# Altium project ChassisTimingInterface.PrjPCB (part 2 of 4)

## Sheet ChassisTimingInterface5.SchDoc: FPGA Interface
size C; DocumentNumber: 6; Revision: C; SheetNumber: 6; SheetTotal: 12
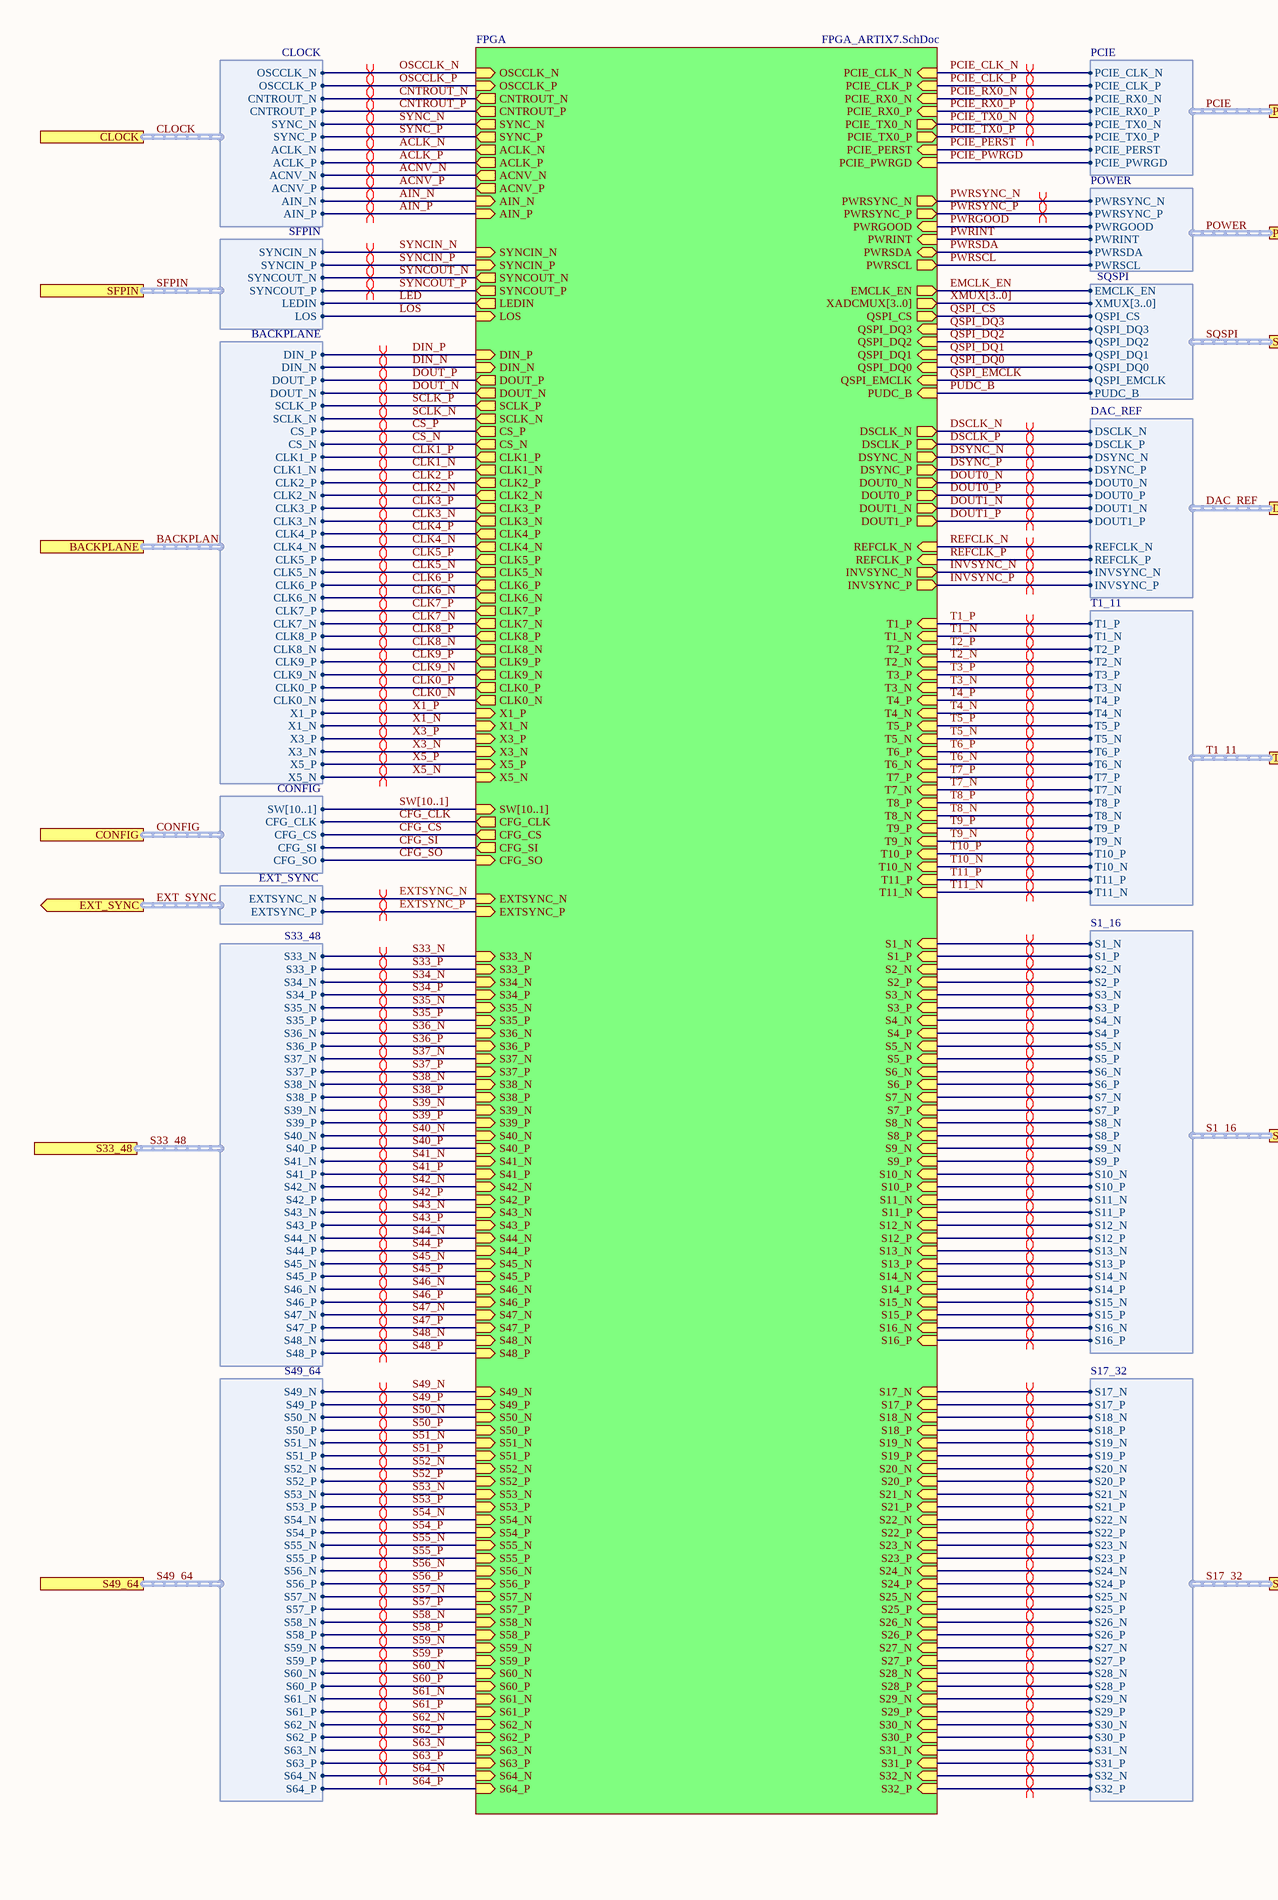
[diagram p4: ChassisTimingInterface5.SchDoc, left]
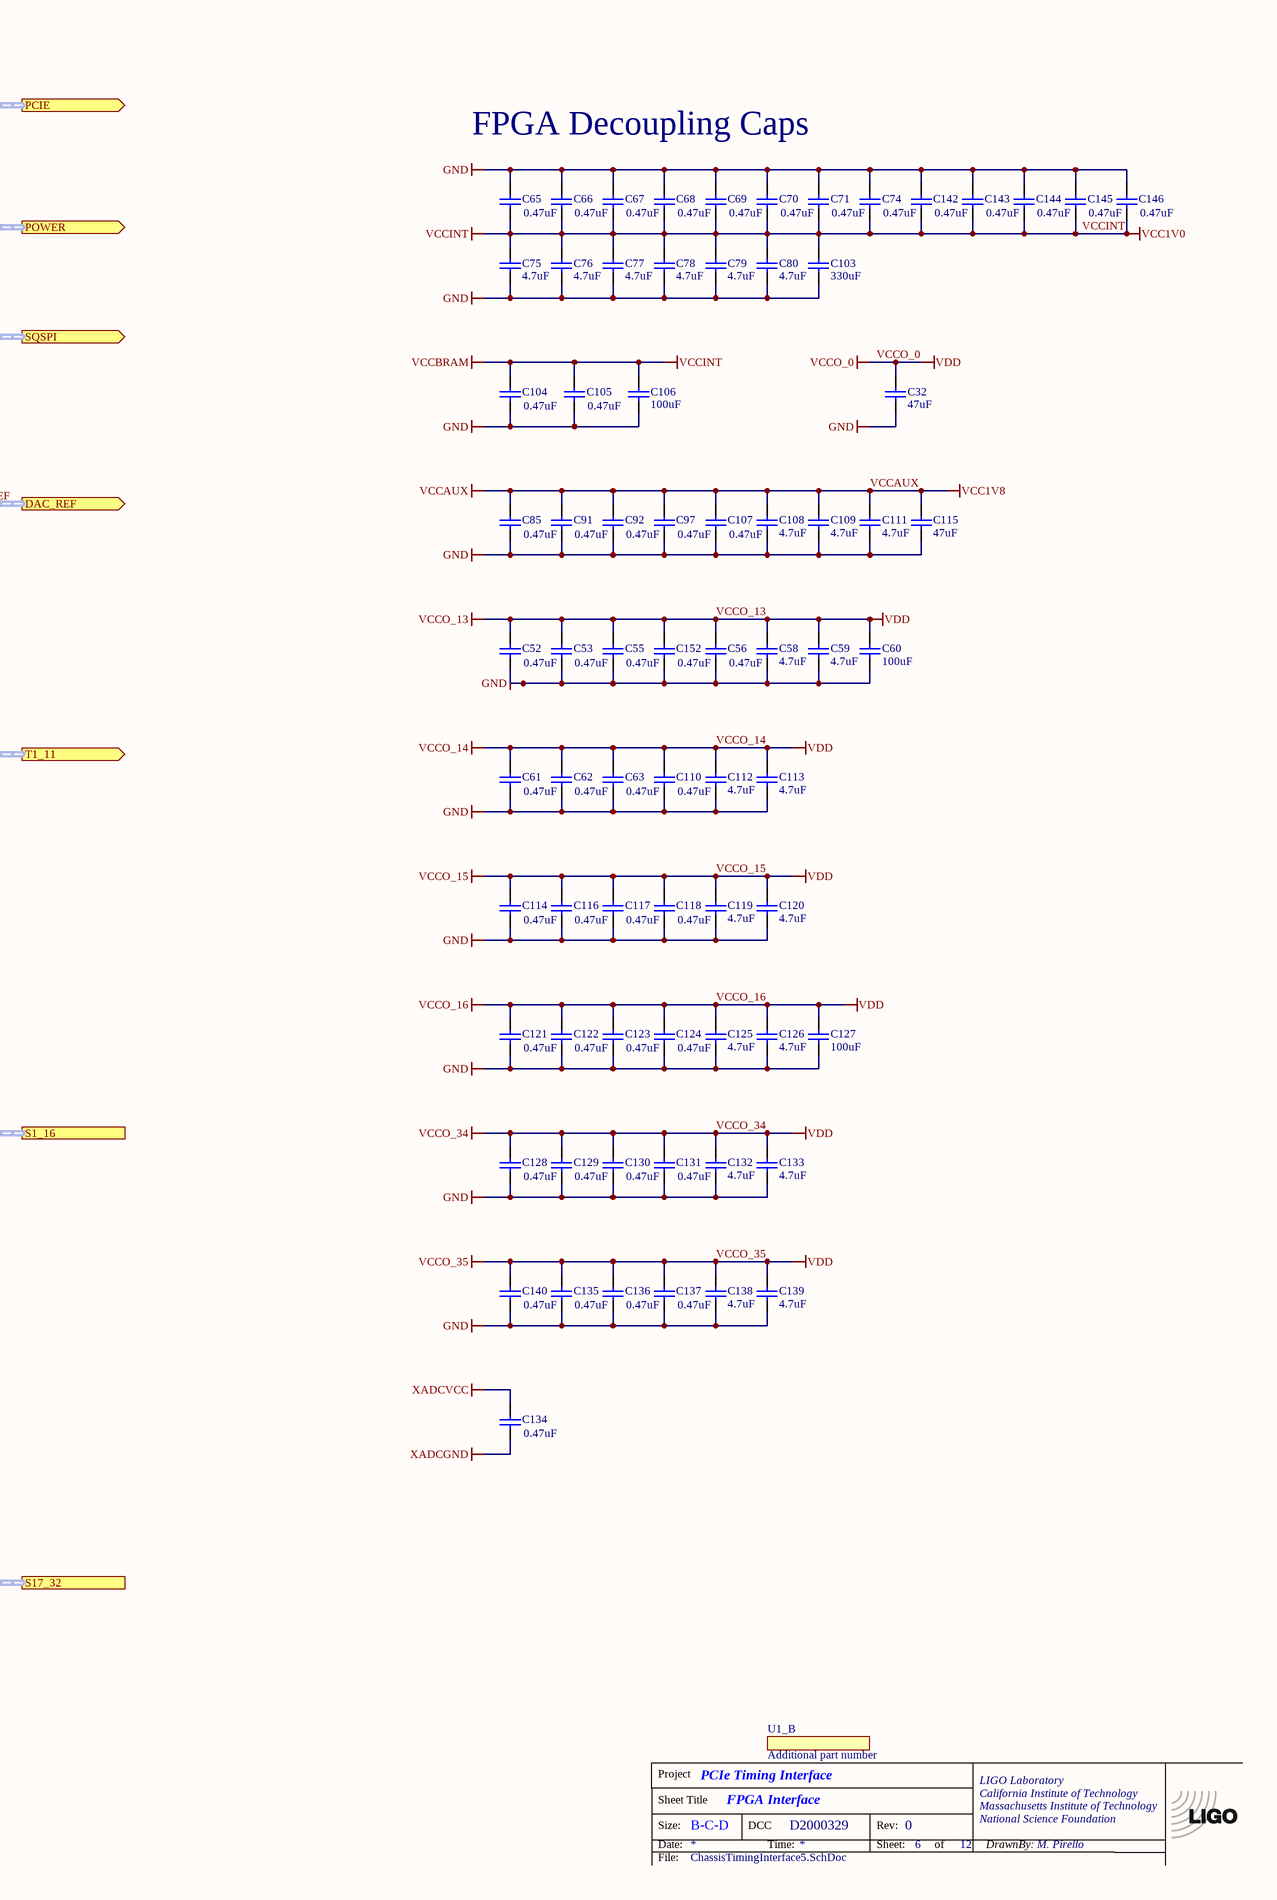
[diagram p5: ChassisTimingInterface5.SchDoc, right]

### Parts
(Parts that share a designator on the sheet are numbered #1, #2 ... from top to bottom, then left to right.)
*?#3  TitleBlock  (value not drawn)  (graphical)
C32  47uF  [CC3225-1210]
C52  0.47uF  [CAPC0603X33X15NL03T05]
C53  0.47uF  [CAPC0603X33X15NL03T05]
C55  0.47uF  [CAPC0603X33X15NL03T05]
C56  0.47uF  [CAPC0603X33X15NL03T05]
C58  4.7uF  [CC1608-0603]
C59  4.7uF  [CC1608-0603]
C60  100uF  [CC3225-1210]
C61  0.47uF  [CAPC0603X33X15NL03T05]
C62  0.47uF  [CAPC0603X33X15NL03T05]
C63  0.47uF  [CAPC0603X33X15NL03T05]
C65  0.47uF  [CAPC0603X33X15NL03T05]
C66  0.47uF  [CAPC0603X33X15NL03T05]
C67  0.47uF  [CAPC0603X33X15NL03T05]
C68  0.47uF  [CAPC0603X33X15NL03T05]
C69  0.47uF  [CAPC0603X33X15NL03T05]
C70  0.47uF  [CAPC0603X33X15NL03T05]
C71  0.47uF  [CAPC0603X33X15NL03T05]
C74  0.47uF  [CAPC0603X33X15NL03T05]
C75  4.7uF  [CC1608-0603]
C76  4.7uF  [CC1608-0603]
C77  4.7uF  [CC1608-0603]
C78  4.7uF  [CC1608-0603]
C79  4.7uF  [CC1608-0603]
C80  4.7uF  [CC1608-0603]
C85  0.47uF  [CAPC0603X33X15NL03T05]
C91  0.47uF  [CAPC0603X33X15NL03T05]
C92  0.47uF  [CAPC0603X33X15NL03T05]
C97  0.47uF  [CAPC0603X33X15NL03T05]
C103  330uF  [CC3225-1210]
C104  0.47uF  [CAPC0603X33X15NL03T05]
C105  0.47uF  [CAPC0603X33X15NL03T05]
C106  100uF  [CC3225-1210]
C107  0.47uF  [CAPC0603X33X15NL03T05]
C108  4.7uF  [CC1608-0603]
C109  4.7uF  [CC1608-0603]
C110  0.47uF  [CAPC0603X33X15NL03T05]
C111  4.7uF  [CC1608-0603]
C112  4.7uF  [CC1608-0603]
C113  4.7uF  [CC1608-0603]
C114  0.47uF  [CAPC0603X33X15NL03T05]
C115  47uF  [CC3225-1210]
C116  0.47uF  [CAPC0603X33X15NL03T05]
C117  0.47uF  [CAPC0603X33X15NL03T05]
C118  0.47uF  [CAPC0603X33X15NL03T05]
C119  4.7uF  [CC1608-0603]
C120  4.7uF  [CC1608-0603]
C121  0.47uF  [CAPC0603X33X15NL03T05]
C122  0.47uF  [CAPC0603X33X15NL03T05]
C123  0.47uF  [CAPC0603X33X15NL03T05]
C124  0.47uF  [CAPC0603X33X15NL03T05]
C125  4.7uF  [CC1608-0603]
C126  4.7uF  [CC1608-0603]
C127  100uF  [CC3225-1210]
C128  0.47uF  [CAPC0603X33X15NL03T05]
C129  0.47uF  [CAPC0603X33X15NL03T05]
C130  0.47uF  [CAPC0603X33X15NL03T05]
C131  0.47uF  [CAPC0603X33X15NL03T05]
C132  4.7uF  [CC1608-0603]
C133  4.7uF  [CC1608-0603]
C134  0.47uF  [CAPC0603X33X15NL03T05]
C135  0.47uF  [CAPC0603X33X15NL03T05]
C136  0.47uF  [CAPC0603X33X15NL03T05]
C137  0.47uF  [CAPC0603X33X15NL03T05]
C138  4.7uF  [CC1608-0603]
C139  4.7uF  [CC1608-0603]
C140  0.47uF  [CAPC0603X33X15NL03T05]
C142  0.47uF  [CAPC0603X33X15NL03T05]
C143  0.47uF  [CAPC0603X33X15NL03T05]
C144  0.47uF  [CAPC0603X33X15NL03T05]
C145  0.47uF  [CAPC0603X33X15NL03T05]
C146  0.47uF  [CAPC0603X33X15NL03T05]
C152  0.47uF  [CAPC0603X33X15NL03T05]
U1_B  Additional part number  (mechanical)

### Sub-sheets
FPGA = FPGA_ARTIX7.SchDoc: SW[10..1] (in), XADCMUX[3..0] (out), S1_N (in), S1_P (in), S2_N (in), S2_P (in), S3_N (in), S3_P (in), S4_N (in), S4_P (in), S5_N (in), S5_P (in), S6_N (in), S6_P (in), S7_N (in), S7_P (in), S8_N (in), S8_P (in), S9_P (in), S9_N (in), S10_P (in), S10_N (in), S11_P (in), S11_N (in), S12_P (in), S12_N (in), S13_P (in), S13_N (in), S14_P (in), S14_N (in), S15_P (in), S15_N (in), S16_P (in), S16_N (in), S33_N (in), S33_P (in), S34_N (in), S34_P (in), S35_N (in), S35_P (in), S36_N (in), S36_P (in), S37_N (in), S37_P (in), S38_N (in), S38_P (in), S39_N (in), S39_P (in), S40_N (in), S40_P (in), S42_N (in), S41_P (in), S42_P (in), S43_N (in), S43_P (in), S44_N (in), S44_P (in), S45_N (in), S45_P (in), S46_N (in), S46_P (in), S47_N (in), S47_P (in), S48_N (in), S48_P (in), S41_N (in), T9_P (in), T9_N (in), T8_P (in), T8_N (in), T7_P (in), T7_N (in), T6_P (in), T6_N (in), T5_P (in), T5_N (in), T4_P (in), T4_N (in), T3_P (in), T3_N (in), T2_P (in), T2_N (in), T11_P (in), T11_N (in), T10_P (in), T10_N (in), T1_P (in), T1_N (in), REFCLK_N (in), REFCLK_P (in), PCIE_PERST (in), PCIE_RX0_N (in), PCIE_TX0_N (out), PCIE_RX0_P (in), PCIE_TX0_P (out), PCIE_CLK_N (in), PCIE_CLK_P (in), PWRSYNC_N (out), PWRSYNC_P (out), PWRINT (in), PWRGOOD (in), PWRSDA (bidir), PWRSCL (out), QSPI_DQ0 (in), QSPI_CS (out), QSPI_DQ2 (in), QSPI_DQ3 (in), QSPI_DQ1 (in), CNTROUT_N (out), CNTROUT_P (out), OSCCLK_N (in), OSCCLK_P (in), SYNC_N (out), SYNC_P (out), ACLK_N (out), ACLK_P (out), ACNV_N (out), ACNV_P (out), AIN_N (in), AIN_P (in), LEDIN (out), LOS (in), SYNCIN_N (in), SYNCIN_P (in), SYNCOUT_N (out), SYNCOUT_P (out), CS_P (out), CS_N (out), SCLK_P (out), SCLK_N (out), DOUT_P (out), DOUT_N (out), DIN_P (in), DIN_N (in), CFG_CLK (out), CFG_CS (out), CFG_SI (out), CFG_SO (in), INVSYNC_N (out), INVSYNC_P (out), CLK9_P (out), CLK9_N (out), CLK8_P (out), CLK8_N (out), CLK7_P (out), CLK7_N (out), CLK6_P (out), CLK6_N (out), CLK5_P (out), CLK5_N (out), CLK4_P (out), CLK4_N (out), CLK3_P (out), CLK3_N (out), CLK2_P (out), CLK2_N (out), CLK0_P (out), CLK0_N (out), CLK1_P (out), CLK1_N (out), X1_P (in), X1_N (in), X3_P (in), X3_N (in), X5_P (in), X5_N (in), S49_N (in), S49_P (in), S50_N (in), S50_P (in), S51_N (in), S51_P (in), S52_N (in), S52_P (in), S53_N (in), S53_P (in), S54_N (in), S54_P (in), S55_N (in), S55_P (in), S56_N (in), S56_P (in), S57_N (in), S57_P (in), S58_N (in), S58_P (in), S59_N (in), S59_P (in), S60_N (in), S60_P (in), S61_N (in), S61_P (in), S62_N (in), S62_P (in), S63_N (in), S63_P (in), S64_N (in), S64_P (in), S29_P (in), S17_N (in), S17_P (in), S18_N (in), S18_P (in), S19_N (in), S19_P (in), S20_N (in), S20_P (in), S21_N (in), S21_P (in), S22_N (in), S22_P (in), S23_N (in), S23_P (in), S24_N (in), S24_P (in), S25_N (in), S25_P (in), S26_N (in), S26_P (in), S27_N (in), S27_P (in), S28_N (in), S28_P (in), S29_N (in), S30_N (in), S30_P (in), S31_N (in), S31_P (in), S32_N (in), S32_P (in), QSPI_EMCLK (in), EXTSYNC_N (in), EXTSYNC_P (in), DOUT0_N (out), DSCLK_P (out), DSCLK_N (out), DOUT0_P (out), DSYNC_N (out), DOUT1_P (out), DSYNC_P (out), DOUT1_N (out), PUDC_B (in), PCIE_PWRGD (in), EMCLK_EN (out)

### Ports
BACKPLANE (harness BACKPLANE), CLOCK (harness CLOCK), CONFIG (harness CONFIG), DAC_REF (out, harness DAC_REF), EXT_SYNC (out, harness EXT_SYNC), PCIE (out, harness PCIE), POWER (out, harness POWER), S1_16 (harness S1_16), S17_32 (harness S17_32), S33_48 (harness S33_48), S49_64 (harness S49_64), SFPIN (harness SFPIN), SQSPI (out, harness SQSPI), T1_11 (out, harness T1_11)

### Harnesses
S1_16: S1_N, S1_P, S2_N, S2_P, S3_N, S3_P, S4_N, S4_P, S5_N, S5_P, S6_N, S6_P, S7_N, S7_P, S8_N, S8_P, S9_N, S9_P, S10_N, S10_P, S11_N, S11_P, S12_N, S12_P, S13_N, S13_P, S14_N, S14_P, S15_N, S15_P, S16_N, S16_P
S17_32: S17_N, S17_P, S18_N, S18_P, S19_N, S19_P, S20_N, S20_P, S21_N, S21_P, S22_N, S22_P, S23_N, S23_P, S24_N, S24_P, S25_N, S25_P, S26_N, S26_P, S27_N, S27_P, S28_N, S28_P, S29_N, S29_P, S30_N, S30_P, S31_N, S31_P, S32_N, S32_P
S33_48: S33_N, S33_P, S34_N, S34_P, S35_N, S35_P, S36_N, S36_P, S37_N, S37_P, S38_N, S38_P, S39_N, S39_P, S40_N, S40_P, S41_N, S41_P, S42_N, S42_P, S43_N, S43_P, S44_N, S44_P, S45_N, S45_P, S46_N, S46_P, S47_N, S47_P, S48_N, S48_P
S49_64: S49_N, S49_P, S50_N, S50_P, S51_N, S51_P, S52_N, S52_P, S53_N, S53_P, S54_N, S54_P, S55_N, S55_P, S56_N, S56_P, S57_N, S57_P, S58_N, S58_P, S59_N, S59_P, S60_N, S60_P, S61_N, S61_P, S62_N, S62_P, S63_N, S63_P, S64_N, S64_P
T1_11: T1_P, T1_N, T2_P, T2_N, T3_P, T3_N, T4_P, T4_N, T5_P, T5_N, T6_P, T6_N, T7_P, T7_N, T8_P, T8_N, T9_P, T9_N, T10_P, T10_N, T11_P, T11_N
BACKPLANE: DIN_P, DIN_N, DOUT_P, DOUT_N, SCLK_P, SCLK_N, CS_P, CS_N, CLK1_P, CLK1_N, CLK2_P, CLK2_N, CLK3_P, CLK3_N, CLK4_P, CLK4_N, CLK5_P, CLK5_N, CLK6_P, CLK6_N, CLK7_P, CLK7_N, CLK8_P, CLK8_N, CLK9_P, CLK9_N, CLK0_P, CLK0_N, X1_P, X1_N, X3_P, X3_N, X5_P, X5_N
SFPIN: SYNCIN_N, SYNCIN_P, SYNCOUT_N, SYNCOUT_P, LEDIN, LOS
CLOCK: OSCCLK_N, OSCCLK_P, CNTROUT_N, CNTROUT_P, SYNC_N, SYNC_P, ACLK_P, ACLK_N, ACNV_P, ACNV_N, AIN_P, AIN_N
CONFIG: CFG_CLK, CFG_CS, CFG_SI, CFG_SO, SW[10..1]
SQSPI: QSPI_CS, QSPI_DQ3, QSPI_DQ2, QSPI_DQ1, QSPI_DQ0, QSPI_EMCLK, PUDC_B, XMUX[3..0], EMCLK_EN
PCIE: PCIE_CLK_N, PCIE_CLK_P, PCIE_RX0_N, PCIE_RX0_P, PCIE_TX0_N, PCIE_TX0_P, PCIE_PERST, PCIE_PWRGD
POWER: PWRSYNC_N, PWRSYNC_P, PWRGOOD, PWRINT, PWRSDA, PWRSCL
DAC_REF: DSCLK_N, DSCLK_P, DSYNC_N, DSYNC_P, DOUT0_N, DOUT0_P, DOUT1_N, DOUT1_P, REFCLK_N, REFCLK_P, INVSYNC_N, INVSYNC_P
EXT_SYNC: EXTSYNC_P, EXTSYNC_N

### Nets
GND: C32.1 C52.1 C53.1 C55.1 C56.1 C58.1 C59.1 C60.1 C61.1 C62.1 C63.1 C65.2 C66.2 C67.2 C68.2 C69.2 C70.2 C71.2 C74.2 C75.1 C76.1 C77.1 C78.1 C79.1 C80.1 C85.1 C91.1 C92.1 C97.1 C103.1 C104.1 C105.1 C106.1 C107.1 C108.1 C109.1 C110.1 C111.1 C112.1 C113.1 C114.1 C115.1 C116.1 C117.1 C118.1 C119.1 C120.1 C121.1 C122.1 C123.1 C124.1 C125.1 C126.1 C127.1 C128.1 C129.1 C130.1 C131.1 C132.1 C133.1 C135.1 C136.1 C137.1 C138.1 C139.1 C140.1 C142.2 C143.2 C144.2 C145.2 C146.2 C152.1
VCC1V8: C85.2 C91.2 C92.2 C97.2 C107.2 C108.2 C109.2 C111.2 C115.2  [also labelled VCCAUX]
VCCINT: C65.1 C66.1 C67.1 C68.1 C69.1 C70.1 C71.1 C74.1 C75.2 C76.2 C77.2 C78.2 C79.2 C80.2 C103.2 C104.2 C105.2 C106.2 C142.1 C143.1 C144.1 C145.1 C146.1  [also labelled VCC1V0, VCCBRAM]
VDD: C32.2 C52.2 C53.2 C55.2 C56.2 C58.2 C59.2 C60.2 C61.2 C62.2 C63.2 C110.2 C112.2 C113.2 C114.2 C116.2 C117.2 C118.2 C119.2 C120.2 C121.2 C122.2 C123.2 C124.2 C125.2 C126.2 C127.2 C128.2 C129.2 C130.2 C131.2 C132.2 C133.2 C135.2 C136.2 C137.2 C138.2 C139.2 C140.2 C152.2  [also labelled VCCO_0, VCCO_13, VCCO_14, VCCO_15, VCCO_16, VCCO_34, VCCO_35]
XADCGND: C134.1
XADCVCC: C134.2
ACLK_N: sheet FPGA/ACLK_N, port CLOCK.ACLK_N  [project net CLOCK.ACLK_N]
ACLK_P: sheet FPGA/ACLK_P, port CLOCK.ACLK_P  [project net CLOCK.ACLK_P]
ACNV_N: sheet FPGA/ACNV_N, port CLOCK.ACNV_N  [project net CLOCK.ACNV_N]
ACNV_P: sheet FPGA/ACNV_P, port CLOCK.ACNV_P  [project net CLOCK.ACNV_P]
AIN_N: sheet FPGA/AIN_N, port CLOCK.AIN_N  [project net CLOCK.AIN_N]
AIN_P: sheet FPGA/AIN_P, port CLOCK.AIN_P  [project net CLOCK.AIN_P]
CFG_CLK: sheet FPGA/CFG_CLK, port CONFIG.CFG_CLK
CFG_CS: sheet FPGA/CFG_CS, port CONFIG.CFG_CS
CFG_SI: sheet FPGA/CFG_SI, port CONFIG.CFG_SI
CFG_SO: sheet FPGA/CFG_SO, port CONFIG.CFG_SO
CLK0_N: sheet FPGA/CLK0_N, port BACKPLANE.CLK0_N  [project net BACKPLANE.CLK0_N]
CLK0_P: sheet FPGA/CLK0_P, port BACKPLANE.CLK0_P  [project net BACKPLANE.CLK0_P]
CLK1_N: sheet FPGA/CLK1_N, port BACKPLANE.CLK1_N  [project net BACKPLANE.CLK1_N]
CLK1_P: sheet FPGA/CLK1_P, port BACKPLANE.CLK1_P  [project net BACKPLANE.CLK1_P]
CLK2_N: sheet FPGA/CLK2_N, port BACKPLANE.CLK2_N  [project net BACKPLANE.CLK2_N]
CLK2_P: sheet FPGA/CLK2_P, port BACKPLANE.CLK2_P  [project net BACKPLANE.CLK2_P]
CLK3_N: sheet FPGA/CLK3_N, port BACKPLANE.CLK3_N  [project net BACKPLANE.CLK3_N]
CLK3_P: sheet FPGA/CLK3_P, port BACKPLANE.CLK3_P  [project net BACKPLANE.CLK3_P]
CLK4_N: sheet FPGA/CLK4_N, port BACKPLANE.CLK4_N  [project net BACKPLANE.CLK4_N]
CLK4_P: sheet FPGA/CLK4_P, port BACKPLANE.CLK4_P  [project net BACKPLANE.CLK4_P]
CLK5_N: sheet FPGA/CLK5_N, port BACKPLANE.CLK5_N  [project net BACKPLANE.CLK5_N]
CLK5_P: sheet FPGA/CLK5_P, port BACKPLANE.CLK5_P  [project net BACKPLANE.CLK5_P]
CLK6_N: sheet FPGA/CLK6_N, port BACKPLANE.CLK6_N  [project net BACKPLANE.CLK6_N]
CLK6_P: sheet FPGA/CLK6_P, port BACKPLANE.CLK6_P  [project net BACKPLANE.CLK6_P]
CLK7_N: sheet FPGA/CLK7_N, port BACKPLANE.CLK7_N  [project net BACKPLANE.CLK7_N]
CLK7_P: sheet FPGA/CLK7_P, port BACKPLANE.CLK7_P  [project net BACKPLANE.CLK7_P]
CLK8_N: sheet FPGA/CLK8_N, port BACKPLANE.CLK8_N  [project net BACKPLANE.CLK8_N]
CLK8_P: sheet FPGA/CLK8_P, port BACKPLANE.CLK8_P  [project net BACKPLANE.CLK8_P]
CLK9_N: sheet FPGA/CLK9_N, port BACKPLANE.CLK9_N  [project net BACKPLANE.CLK9_N]
CLK9_P: sheet FPGA/CLK9_P, port BACKPLANE.CLK9_P  [project net BACKPLANE.CLK9_P]
CNTROUT_N: sheet FPGA/CNTROUT_N, port CLOCK.CNTROUT_N  [project net CLOCK.CNTROUT_N]
CNTROUT_P: sheet FPGA/CNTROUT_P, port CLOCK.CNTROUT_P  [project net CLOCK.CNTROUT_P]
CS_N: sheet FPGA/CS_N, port BACKPLANE.CS_N  [project net BACKPLANE.CS_N]
CS_P: sheet FPGA/CS_P, port BACKPLANE.CS_P  [project net BACKPLANE.CS_P]
DIN_N: sheet FPGA/DIN_N, port BACKPLANE.DIN_N  [project net BACKPLANE.DIN_N]
DIN_P: sheet FPGA/DIN_P, port BACKPLANE.DIN_P  [project net BACKPLANE.DIN_P]
DOUT0_N: sheet FPGA/DOUT0_N, port DAC_REF.DOUT0_N  [project net DAC_REF.DOUT0_N]
DOUT0_P: sheet FPGA/DOUT0_P, port DAC_REF.DOUT0_P  [project net DAC_REF.DOUT0_P]
DOUT1_N: sheet FPGA/DOUT1_N, port DAC_REF.DOUT1_N  [project net DAC_REF.DOUT1_N]
DOUT1_P: sheet FPGA/DOUT1_P, port DAC_REF.DOUT1_P  [project net DAC_REF.DOUT1_P]
DOUT_N: sheet FPGA/DOUT_N, port BACKPLANE.DOUT_N  [project net BACKPLANE.DOUT_N]
DOUT_P: sheet FPGA/DOUT_P, port BACKPLANE.DOUT_P  [project net BACKPLANE.DOUT_P]
DSCLK_N: sheet FPGA/DSCLK_N, port DAC_REF.DSCLK_N  [project net DAC_REF.DSCLK_N]
DSCLK_P: sheet FPGA/DSCLK_P, port DAC_REF.DSCLK_P  [project net DAC_REF.DSCLK_P]
DSYNC_N: sheet FPGA/DSYNC_N, port DAC_REF.DSYNC_N  [project net DAC_REF.DSYNC_N]
DSYNC_P: sheet FPGA/DSYNC_P, port DAC_REF.DSYNC_P  [project net DAC_REF.DSYNC_P]
EMCLK_EN: sheet FPGA/EMCLK_EN, port SQSPI.EMCLK_EN  [project net SQSPI.EMCLK_EN]
EXTSYNC_N: sheet FPGA/EXTSYNC_N, port EXT_SYNC.EXTSYNC_N  [project net EXT_SYNC.EXTSYNC_N]
EXTSYNC_P: sheet FPGA/EXTSYNC_P, port EXT_SYNC.EXTSYNC_P  [project net EXT_SYNC.EXTSYNC_P]
INVSYNC_N: sheet FPGA/INVSYNC_N, port DAC_REF.INVSYNC_N  [project net DAC_REF.INVSYNC_N]
INVSYNC_P: sheet FPGA/INVSYNC_P, port DAC_REF.INVSYNC_P  [project net DAC_REF.INVSYNC_P]
LED: sheet FPGA/LEDIN, port SFPIN.LEDIN  [project net SFPIN.LEDIN]
LOS: sheet FPGA/LOS, port SFPIN.LOS  [project net SFPIN.LOS]
OSCCLK_N: sheet FPGA/OSCCLK_N, port CLOCK.OSCCLK_N  [project net CLOCK.OSCCLK_N]
OSCCLK_P: sheet FPGA/OSCCLK_P, port CLOCK.OSCCLK_P  [project net CLOCK.OSCCLK_P]
PCIE_CLK_N: sheet FPGA/PCIE_CLK_N, port PCIE.PCIE_CLK_N  [project net PCIE.PCIE_CLK_N]
PCIE_CLK_P: sheet FPGA/PCIE_CLK_P, port PCIE.PCIE_CLK_P  [project net PCIE.PCIE_CLK_P]
PCIE_PERST: sheet FPGA/PCIE_PERST, port PCIE.PCIE_PERST  [project net PCIE.PCIE_PERST]
PCIE_PWRGD: sheet FPGA/PCIE_PWRGD, port PCIE.PCIE_PWRGD  [project net PCIE.PCIE_PWRGD]
PCIE_RX0_N: sheet FPGA/PCIE_RX0_N, port PCIE.PCIE_RX0_N  [project net PCIE.PCIE_RX0_N]
PCIE_RX0_P: sheet FPGA/PCIE_RX0_P, port PCIE.PCIE_RX0_P  [project net PCIE.PCIE_RX0_P]
PCIE_TX0_N: sheet FPGA/PCIE_TX0_N, port PCIE.PCIE_TX0_N  [project net PCIE.PCIE_TX0_N]
PCIE_TX0_P: sheet FPGA/PCIE_TX0_P, port PCIE.PCIE_TX0_P  [project net PCIE.PCIE_TX0_P]
PUDC_B: sheet FPGA/PUDC_B, port SQSPI.PUDC_B  [project net SQSPI.PUDC_B]
PWRGOOD: sheet FPGA/PWRGOOD, port POWER.PWRGOOD  [project net POWER.PWRGOOD]
PWRINT: sheet FPGA/PWRINT, port POWER.PWRINT  [project net POWER.PWRINT]
PWRSCL: sheet FPGA/PWRSCL, port POWER.PWRSCL  [project net POWER.PWRSCL]
PWRSDA: sheet FPGA/PWRSDA, port POWER.PWRSDA  [project net POWER.PWRSDA]
PWRSYNC_N: sheet FPGA/PWRSYNC_N, port POWER.PWRSYNC_N  [project net POWER.PWRSYNC_N]
PWRSYNC_P: sheet FPGA/PWRSYNC_P, port POWER.PWRSYNC_P  [project net POWER.PWRSYNC_P]
QSPI_CS: sheet FPGA/QSPI_CS, port SQSPI.QSPI_CS  [project net SQSPI.QSPI_CS]
QSPI_DQ0: sheet FPGA/QSPI_DQ0, port SQSPI.QSPI_DQ0  [project net SQSPI.QSPI_DQ0]
QSPI_DQ1: sheet FPGA/QSPI_DQ1, port SQSPI.QSPI_DQ1  [project net SQSPI.QSPI_DQ1]
QSPI_DQ2: sheet FPGA/QSPI_DQ2, port SQSPI.QSPI_DQ2  [project net SQSPI.QSPI_DQ2]
QSPI_DQ3: sheet FPGA/QSPI_DQ3, port SQSPI.QSPI_DQ3  [project net SQSPI.QSPI_DQ3]
QSPI_EMCLK: sheet FPGA/QSPI_EMCLK, port SQSPI.QSPI_EMCLK  [project net SQSPI.QSPI_EMCLK]
REFCLK_N: sheet FPGA/REFCLK_N, port DAC_REF.REFCLK_N  [project net DAC_REF.REFCLK_N]
REFCLK_P: sheet FPGA/REFCLK_P, port DAC_REF.REFCLK_P  [project net DAC_REF.REFCLK_P]
S1_16.S1_N: sheet FPGA/S1_N, port S1_16.S1_N
S1_16.S1_P: sheet FPGA/S1_P, port S1_16.S1_P
S1_16.S2_N: sheet FPGA/S2_N, port S1_16.S2_N
S1_16.S2_P: sheet FPGA/S2_P, port S1_16.S2_P
S1_16.S3_N: sheet FPGA/S3_N, port S1_16.S3_N
S1_16.S3_P: sheet FPGA/S3_P, port S1_16.S3_P
S1_16.S4_N: sheet FPGA/S4_N, port S1_16.S4_N
S1_16.S4_P: sheet FPGA/S4_P, port S1_16.S4_P
S1_16.S5_N: sheet FPGA/S5_N, port S1_16.S5_N
S1_16.S5_P: sheet FPGA/S5_P, port S1_16.S5_P
S1_16.S6_N: sheet FPGA/S6_N, port S1_16.S6_N
S1_16.S6_P: sheet FPGA/S6_P, port S1_16.S6_P
S1_16.S7_N: sheet FPGA/S7_N, port S1_16.S7_N
S1_16.S7_P: sheet FPGA/S7_P, port S1_16.S7_P
S1_16.S8_N: sheet FPGA/S8_N, port S1_16.S8_N
S1_16.S8_P: sheet FPGA/S8_P, port S1_16.S8_P
S1_16.S9_N: sheet FPGA/S9_N, port S1_16.S9_N
S1_16.S9_P: sheet FPGA/S9_P, port S1_16.S9_P
S10_N: sheet FPGA/S10_N, port S1_16.S10_N
S10_P: sheet FPGA/S10_P, port S1_16.S10_P
S11_N: sheet FPGA/S11_N, port S1_16.S11_N
S11_P: sheet FPGA/S11_P, port S1_16.S11_P
S12_N: sheet FPGA/S12_N, port S1_16.S12_N
S12_P: sheet FPGA/S12_P, port S1_16.S12_P
S13_N: sheet FPGA/S13_N, port S1_16.S13_N
S13_P: sheet FPGA/S13_P, port S1_16.S13_P
S14_N: sheet FPGA/S14_N, port S1_16.S14_N
S14_P: sheet FPGA/S14_P, port S1_16.S14_P
S15_N: sheet FPGA/S15_N, port S1_16.S15_N
S15_P: sheet FPGA/S15_P, port S1_16.S15_P
S16_N: sheet FPGA/S16_N, port S1_16.S16_N
S16_P: sheet FPGA/S16_P, port S1_16.S16_P
S17_32.S17_N: sheet FPGA/S17_N, port S17_32.S17_N
S17_32.S17_P: sheet FPGA/S17_P, port S17_32.S17_P
S17_32.S18_N: sheet FPGA/S18_N, port S17_32.S18_N
S17_32.S18_P: sheet FPGA/S18_P, port S17_32.S18_P
S17_32.S19_N: sheet FPGA/S19_N, port S17_32.S19_N
S17_32.S19_P: sheet FPGA/S19_P, port S17_32.S19_P
S17_32.S20_N: sheet FPGA/S20_N, port S17_32.S20_N
S17_32.S20_P: sheet FPGA/S20_P, port S17_32.S20_P
S17_32.S21_N: sheet FPGA/S21_N, port S17_32.S21_N
S17_32.S21_P: sheet FPGA/S21_P, port S17_32.S21_P
S17_32.S22_N: sheet FPGA/S22_N, port S17_32.S22_N
S17_32.S22_P: sheet FPGA/S22_P, port S17_32.S22_P
S17_32.S23_N: sheet FPGA/S23_N, port S17_32.S23_N
S17_32.S23_P: sheet FPGA/S23_P, port S17_32.S23_P
S17_32.S24_N: sheet FPGA/S24_N, port S17_32.S24_N
S17_32.S24_P: sheet FPGA/S24_P, port S17_32.S24_P
S17_32.S25_N: sheet FPGA/S25_N, port S17_32.S25_N
S17_32.S25_P: sheet FPGA/S25_P, port S17_32.S25_P
S17_32.S26_N: sheet FPGA/S26_N, port S17_32.S26_N
S17_32.S26_P: sheet FPGA/S26_P, port S17_32.S26_P
S17_32.S27_N: sheet FPGA/S27_N, port S17_32.S27_N
S17_32.S27_P: sheet FPGA/S27_P, port S17_32.S27_P
S17_32.S28_N: sheet FPGA/S28_N, port S17_32.S28_N
S17_32.S28_P: sheet FPGA/S28_P, port S17_32.S28_P
S17_32.S29_N: sheet FPGA/S29_N, port S17_32.S29_N
S17_32.S29_P: sheet FPGA/S29_P, port S17_32.S29_P
S17_32.S30_N: sheet FPGA/S30_N, port S17_32.S30_N
S17_32.S30_P: sheet FPGA/S30_P, port S17_32.S30_P
S17_32.S31_N: sheet FPGA/S31_N, port S17_32.S31_N
S17_32.S31_P: sheet FPGA/S31_P, port S17_32.S31_P
S17_32.S32_N: sheet FPGA/S32_N, port S17_32.S32_N
S17_32.S32_P: sheet FPGA/S32_P, port S17_32.S32_P
S33_N: sheet FPGA/S33_N, port S33_48.S33_N  [project net S33_48.S33_N]
S33_P: sheet FPGA/S33_P, port S33_48.S33_P  [project net S33_48.S33_P]
S34_N: sheet FPGA/S34_N, port S33_48.S34_N  [project net S33_48.S34_N]
S34_P: sheet FPGA/S34_P, port S33_48.S34_P  [project net S33_48.S34_P]
S35_N: sheet FPGA/S35_N, port S33_48.S35_N  [project net S33_48.S35_N]
S35_P: sheet FPGA/S35_P, port S33_48.S35_P  [project net S33_48.S35_P]
S36_N: sheet FPGA/S36_N, port S33_48.S36_N  [project net S33_48.S36_N]
S36_P: sheet FPGA/S36_P, port S33_48.S36_P  [project net S33_48.S36_P]
S37_N: sheet FPGA/S37_N, port S33_48.S37_N  [project net S33_48.S37_N]
S37_P: sheet FPGA/S37_P, port S33_48.S37_P  [project net S33_48.S37_P]
S38_N: sheet FPGA/S38_N, port S33_48.S38_N  [project net S33_48.S38_N]
S38_P: sheet FPGA/S38_P, port S33_48.S38_P  [project net S33_48.S38_P]
S39_N: sheet FPGA/S39_N, port S33_48.S39_N  [project net S33_48.S39_N]
S39_P: sheet FPGA/S39_P, port S33_48.S39_P  [project net S33_48.S39_P]
S40_N: sheet FPGA/S40_N, port S33_48.S40_N  [project net S33_48.S40_N]
S40_P: sheet FPGA/S40_P, port S33_48.S40_P  [project net S33_48.S40_P]
S41_N: sheet FPGA/S41_N, port S33_48.S41_N  [project net S33_48.S41_N]
S41_P: sheet FPGA/S41_P, port S33_48.S41_P  [project net S33_48.S41_P]
S42_N: sheet FPGA/S42_N, port S33_48.S42_N  [project net S33_48.S42_N]
S42_P: sheet FPGA/S42_P, port S33_48.S42_P  [project net S33_48.S42_P]
S43_N: sheet FPGA/S43_N, port S33_48.S43_N  [project net S33_48.S43_N]
S43_P: sheet FPGA/S43_P, port S33_48.S43_P  [project net S33_48.S43_P]
S44_N: sheet FPGA/S44_N, port S33_48.S44_N  [project net S33_48.S44_N]
S44_P: sheet FPGA/S44_P, port S33_48.S44_P  [project net S33_48.S44_P]
S45_N: sheet FPGA/S45_N, port S33_48.S45_N  [project net S33_48.S45_N]
S45_P: sheet FPGA/S45_P, port S33_48.S45_P  [project net S33_48.S45_P]
S46_N: sheet FPGA/S46_N, port S33_48.S46_N  [project net S33_48.S46_N]
S46_P: sheet FPGA/S46_P, port S33_48.S46_P  [project net S33_48.S46_P]
S47_N: sheet FPGA/S47_N, port S33_48.S47_N  [project net S33_48.S47_N]
S47_P: sheet FPGA/S47_P, port S33_48.S47_P  [project net S33_48.S47_P]
S48_N: sheet FPGA/S48_N, port S33_48.S48_N  [project net S33_48.S48_N]
S48_P: sheet FPGA/S48_P, port S33_48.S48_P  [project net S33_48.S48_P]
S49_N: sheet FPGA/S49_N, port S49_64.S49_N  [project net S49_64.S49_N]
S49_P: sheet FPGA/S49_P, port S49_64.S49_P  [project net S49_64.S49_P]
S50_N: sheet FPGA/S50_N, port S49_64.S50_N  [project net S49_64.S50_N]
S50_P: sheet FPGA/S50_P, port S49_64.S50_P  [project net S49_64.S50_P]
S51_N: sheet FPGA/S51_N, port S49_64.S51_N  [project net S49_64.S51_N]
S51_P: sheet FPGA/S51_P, port S49_64.S51_P  [project net S49_64.S51_P]
S52_N: sheet FPGA/S52_N, port S49_64.S52_N  [project net S49_64.S52_N]
S52_P: sheet FPGA/S52_P, port S49_64.S52_P  [project net S49_64.S52_P]
S53_N: sheet FPGA/S53_N, port S49_64.S53_N  [project net S49_64.S53_N]
S53_P: sheet FPGA/S53_P, port S49_64.S53_P  [project net S49_64.S53_P]
S54_N: sheet FPGA/S54_N, port S49_64.S54_N  [project net S49_64.S54_N]
S54_P: sheet FPGA/S54_P, port S49_64.S54_P  [project net S49_64.S54_P]
S55_N: sheet FPGA/S55_N, port S49_64.S55_N  [project net S49_64.S55_N]
S55_P: sheet FPGA/S55_P, port S49_64.S55_P  [project net S49_64.S55_P]
S56_N: sheet FPGA/S56_N, port S49_64.S56_N  [project net S49_64.S56_N]
S56_P: sheet FPGA/S56_P, port S49_64.S56_P  [project net S49_64.S56_P]
S57_N: sheet FPGA/S57_N, port S49_64.S57_N  [project net S49_64.S57_N]
S57_P: sheet FPGA/S57_P, port S49_64.S57_P  [project net S49_64.S57_P]
S58_N: sheet FPGA/S58_N, port S49_64.S58_N  [project net S49_64.S58_N]
S58_P: sheet FPGA/S58_P, port S49_64.S58_P  [project net S49_64.S58_P]
S59_N: sheet FPGA/S59_N, port S49_64.S59_N  [project net S49_64.S59_N]
S59_P: sheet FPGA/S59_P, port S49_64.S59_P  [project net S49_64.S59_P]
S60_N: sheet FPGA/S60_N, port S49_64.S60_N  [project net S49_64.S60_N]
S60_P: sheet FPGA/S60_P, port S49_64.S60_P  [project net S49_64.S60_P]
S61_N: sheet FPGA/S61_N, port S49_64.S61_N  [project net S49_64.S61_N]
S61_P: sheet FPGA/S61_P, port S49_64.S61_P  [project net S49_64.S61_P]
S62_N: sheet FPGA/S62_N, port S49_64.S62_N  [project net S49_64.S62_N]
S62_P: sheet FPGA/S62_P, port S49_64.S62_P  [project net S49_64.S62_P]
S63_N: sheet FPGA/S63_N, port S49_64.S63_N  [project net S49_64.S63_N]
S63_P: sheet FPGA/S63_P, port S49_64.S63_P  [project net S49_64.S63_P]
S64_N: sheet FPGA/S64_N, port S49_64.S64_N  [project net S49_64.S64_N]
S64_P: sheet FPGA/S64_P, port S49_64.S64_P  [project net S49_64.S64_P]
SCLK_N: sheet FPGA/SCLK_N, port BACKPLANE.SCLK_N  [project net BACKPLANE.SCLK_N]
SCLK_P: sheet FPGA/SCLK_P, port BACKPLANE.SCLK_P  [project net BACKPLANE.SCLK_P]
SYNC_N: sheet FPGA/SYNC_N, port CLOCK.SYNC_N  [project net CLOCK.SYNC_N]
SYNC_P: sheet FPGA/SYNC_P, port CLOCK.SYNC_P  [project net CLOCK.SYNC_P]
SYNCIN_N: sheet FPGA/SYNCIN_N, port SFPIN.SYNCIN_N  [project net SFPIN.SYNCIN_N]
SYNCIN_P: sheet FPGA/SYNCIN_P, port SFPIN.SYNCIN_P  [project net SFPIN.SYNCIN_P]
SYNCOUT_N: sheet FPGA/SYNCOUT_N, port SFPIN.SYNCOUT_N  [project net SFPIN.SYNCOUT_N]
SYNCOUT_P: sheet FPGA/SYNCOUT_P, port SFPIN.SYNCOUT_P  [project net SFPIN.SYNCOUT_P]
T1_N: sheet FPGA/T1_N, port T1_11.T1_N  [project net T1_11.T1_N]
T1_P: sheet FPGA/T1_P, port T1_11.T1_P  [project net T1_11.T1_P]
T2_N: sheet FPGA/T2_N, port T1_11.T2_N  [project net T1_11.T2_N]
T2_P: sheet FPGA/T2_P, port T1_11.T2_P  [project net T1_11.T2_P]
T3_N: sheet FPGA/T3_N, port T1_11.T3_N  [project net T1_11.T3_N]
T3_P: sheet FPGA/T3_P, port T1_11.T3_P  [project net T1_11.T3_P]
T4_N: sheet FPGA/T4_N, port T1_11.T4_N  [project net T1_11.T4_N]
T4_P: sheet FPGA/T4_P, port T1_11.T4_P  [project net T1_11.T4_P]
T5_N: sheet FPGA/T5_N, port T1_11.T5_N  [project net T1_11.T5_N]
T5_P: sheet FPGA/T5_P, port T1_11.T5_P  [project net T1_11.T5_P]
T6_N: sheet FPGA/T6_N, port T1_11.T6_N  [project net T1_11.T6_N]
T6_P: sheet FPGA/T6_P, port T1_11.T6_P  [project net T1_11.T6_P]
T7_N: sheet FPGA/T7_N, port T1_11.T7_N  [project net T1_11.T7_N]
T7_P: sheet FPGA/T7_P, port T1_11.T7_P  [project net T1_11.T7_P]
T8_N: sheet FPGA/T8_N, port T1_11.T8_N  [project net T1_11.T8_N]
T8_P: sheet FPGA/T8_P, port T1_11.T8_P  [project net T1_11.T8_P]
T9_N: sheet FPGA/T9_N, port T1_11.T9_N  [project net T1_11.T9_N]
T9_P: sheet FPGA/T9_P, port T1_11.T9_P  [project net T1_11.T9_P]
T10_N: sheet FPGA/T10_N, port T1_11.T10_N
T10_P: sheet FPGA/T10_P, port T1_11.T10_P
T11_N: sheet FPGA/T11_N, port T1_11.T11_N
T11_P: sheet FPGA/T11_P, port T1_11.T11_P
X1_N: sheet FPGA/X1_N, port BACKPLANE.X1_N  [project net BACKPLANE.X1_N]
X1_P: sheet FPGA/X1_P, port BACKPLANE.X1_P  [project net BACKPLANE.X1_P]
X3_N: sheet FPGA/X3_N, port BACKPLANE.X3_N  [project net BACKPLANE.X3_N]
X3_P: sheet FPGA/X3_P, port BACKPLANE.X3_P  [project net BACKPLANE.X3_P]
X5_N: sheet FPGA/X5_N, port BACKPLANE.X5_N  [project net BACKPLANE.X5_N]
X5_P: sheet FPGA/X5_P, port BACKPLANE.X5_P  [project net BACKPLANE.X5_P]

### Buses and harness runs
bus SW[10..1] = sheet FPGA/SW[10..1]
bus XMUX[3..0] = sheet FPGA/XADCMUX[3..0]
harness BACKPLANE = port BACKPLANE
harness CLOCK = port CLOCK
harness CONFIG = port CONFIG
harness DAC_REF = port DAC_REF
harness EXT_SYNC = port EXT_SYNC
harness PCIE = port PCIE
harness POWER = port POWER
harness S1_16 = port S1_16
harness S17_32 = port S17_32
harness S33_48 = port S33_48
harness S49_64 = port S49_64
harness SFPIN = port SFPIN
harness SQSPI = port SQSPI
harness T1_11 = port T1_11

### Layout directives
differential pair: BACKPLANE.CLK0_N, BACKPLANE.CLK0_P, BACKPLANE.CLK1_N, BACKPLANE.CLK1_P, BACKPLANE.CLK2_N, BACKPLANE.CLK2_P, BACKPLANE.CLK3_N, BACKPLANE.CLK3_P, BACKPLANE.CLK4_N, BACKPLANE.CLK4_P, BACKPLANE.CLK5_N, BACKPLANE.CLK5_P, BACKPLANE.CLK6_N, BACKPLANE.CLK6_P, BACKPLANE.CLK7_N, BACKPLANE.CLK7_P, BACKPLANE.CLK8_N, BACKPLANE.CLK8_P, BACKPLANE.CLK9_N, BACKPLANE.CLK9_P, BACKPLANE.CS_N, BACKPLANE.CS_P, BACKPLANE.DIN_N, BACKPLANE.DIN_P, BACKPLANE.DOUT_N, BACKPLANE.DOUT_P, BACKPLANE.SCLK_N, BACKPLANE.SCLK_P, BACKPLANE.X1_N, BACKPLANE.X1_P, BACKPLANE.X3_N, BACKPLANE.X3_P, BACKPLANE.X5_N, BACKPLANE.X5_P, CLOCK.ACLK_N, CLOCK.ACLK_P, CLOCK.ACNV_N, CLOCK.ACNV_P, CLOCK.AIN_N, CLOCK.AIN_P, CLOCK.CNTROUT_N, CLOCK.CNTROUT_P, CLOCK.OSCCLK_N, CLOCK.OSCCLK_P, CLOCK.SYNC_N, CLOCK.SYNC_P, DAC_REF.DOUT0_N, DAC_REF.DOUT0_P, DAC_REF.DOUT1_N, DAC_REF.DOUT1_P, DAC_REF.DSCLK_N, DAC_REF.DSCLK_P, DAC_REF.DSYNC_N, DAC_REF.DSYNC_P, DAC_REF.INVSYNC_N, DAC_REF.INVSYNC_P, DAC_REF.REFCLK_N, DAC_REF.REFCLK_P, EXT_SYNC.EXTSYNC_N, EXT_SYNC.EXTSYNC_P, PCIE.PCIE_CLK_N, PCIE.PCIE_CLK_P, PCIE.PCIE_RX0_N, PCIE.PCIE_RX0_P, PCIE.PCIE_TX0_N, PCIE.PCIE_TX0_P, POWER.PWRSYNC_N, POWER.PWRSYNC_P, S1_16.S1_N, S1_16.S1_P, S1_16.S2_N, S1_16.S2_P, S1_16.S3_N, S1_16.S3_P, S1_16.S4_N, S1_16.S4_P, S1_16.S5_N, S1_16.S5_P, S1_16.S6_N, S1_16.S6_P, S1_16.S7_N, S1_16.S7_P, S1_16.S8_N, S1_16.S8_P, S1_16.S9_N, S1_16.S9_P, S10_N, S10_P, S11_N, S11_P, S12_N, S12_P, S13_N, S13_P, S14_N, S14_P, S15_N, S15_P, S16_N, S16_P, S17_32.S17_N, S17_32.S17_P, S17_32.S18_N, S17_32.S18_P, S17_32.S19_N, S17_32.S19_P, S17_32.S20_N, S17_32.S20_P, S17_32.S21_N, S17_32.S21_P, S17_32.S22_N, S17_32.S22_P, S17_32.S23_N, S17_32.S23_P, S17_32.S24_N, S17_32.S24_P, S17_32.S25_N, S17_32.S25_P, S17_32.S26_N, S17_32.S26_P, S17_32.S27_N, S17_32.S27_P, S17_32.S28_N, S17_32.S28_P, S17_32.S29_N, S17_32.S29_P, S17_32.S30_N, S17_32.S30_P, S17_32.S31_N, S17_32.S31_P, S17_32.S32_N, S17_32.S32_P, S33_48.S33_N, S33_48.S33_P, S33_48.S34_N, S33_48.S34_P, S33_48.S35_N, S33_48.S35_P, S33_48.S36_N, S33_48.S36_P, S33_48.S37_N, S33_48.S37_P, S33_48.S38_N, S33_48.S38_P, S33_48.S39_N, S33_48.S39_P, S33_48.S40_N, S33_48.S40_P, S33_48.S41_N, S33_48.S41_P, S33_48.S42_N, S33_48.S42_P, S33_48.S43_N, S33_48.S43_P, S33_48.S44_N, S33_48.S44_P, S33_48.S45_N, S33_48.S45_P, S33_48.S46_N, S33_48.S46_P, S33_48.S47_N, S33_48.S47_P, S33_48.S48_N, S33_48.S48_P, S49_64.S49_N, S49_64.S49_P, S49_64.S50_N, S49_64.S50_P, S49_64.S51_N, S49_64.S51_P, S49_64.S52_N, S49_64.S52_P, S49_64.S53_N, S49_64.S53_P, S49_64.S54_N, S49_64.S54_P, S49_64.S55_N, S49_64.S55_P, S49_64.S56_N, S49_64.S56_P, S49_64.S57_N, S49_64.S57_P, S49_64.S58_N, S49_64.S58_P, S49_64.S59_N, S49_64.S59_P, S49_64.S60_N, S49_64.S60_P, S49_64.S61_N, S49_64.S61_P, S49_64.S62_N, S49_64.S62_P, S49_64.S63_N, S49_64.S63_P, S49_64.S64_N, SFPIN.SYNCIN_N, SFPIN.SYNCIN_P, SFPIN.SYNCOUT_N, SFPIN.SYNCOUT_P, T1_11.T1_N, T1_11.T1_P, T1_11.T2_N, T1_11.T2_P, T1_11.T3_N, T1_11.T3_P, T1_11.T4_N, T1_11.T4_P, T1_11.T5_N, T1_11.T5_P, T1_11.T6_N, T1_11.T6_P, T1_11.T7_N, T1_11.T7_P, T1_11.T8_N, T1_11.T8_P, T1_11.T9_N, T1_11.T9_P, T10_N, T10_P, T11_N, T11_P

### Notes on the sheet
- FPGA Decoupling Caps

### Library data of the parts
C32 C115 = ChipCap: Capacitor, surface mount; Part Number: 399-5516-1-ND; Tolerance: 10%
C52 C53 C55 C56 C61-C63 C65-C71 C74 C85 C91 C92 C97 C104 C105 C107 C110 C114 C116-C118 C121-C124 C128-C131 C134-C137 C140 C142-C146 C152 = CMP-2010-00306-1: Part Number: CL03A474MR3NNNC; Manufacturer: Samsung
C58 C59 C75-C80 C108 C109 C111-C113 C119 C120 C125 C126 C132 C133 C138 C139 = ChipCap: Capacitor, surface mount; Part Number: 587-5870-1-ND; Tolerance: 10%
C60 C106 C127 = ChipCap: Capacitor, surface mount; Part Number: 587-4317-1-ND; Tolerance: 10%
C103 = ChipCap: Capacitor, surface mount; Part Number: 490-13976-1-ND (4V); Tolerance: 10%
U1_B = Partlist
